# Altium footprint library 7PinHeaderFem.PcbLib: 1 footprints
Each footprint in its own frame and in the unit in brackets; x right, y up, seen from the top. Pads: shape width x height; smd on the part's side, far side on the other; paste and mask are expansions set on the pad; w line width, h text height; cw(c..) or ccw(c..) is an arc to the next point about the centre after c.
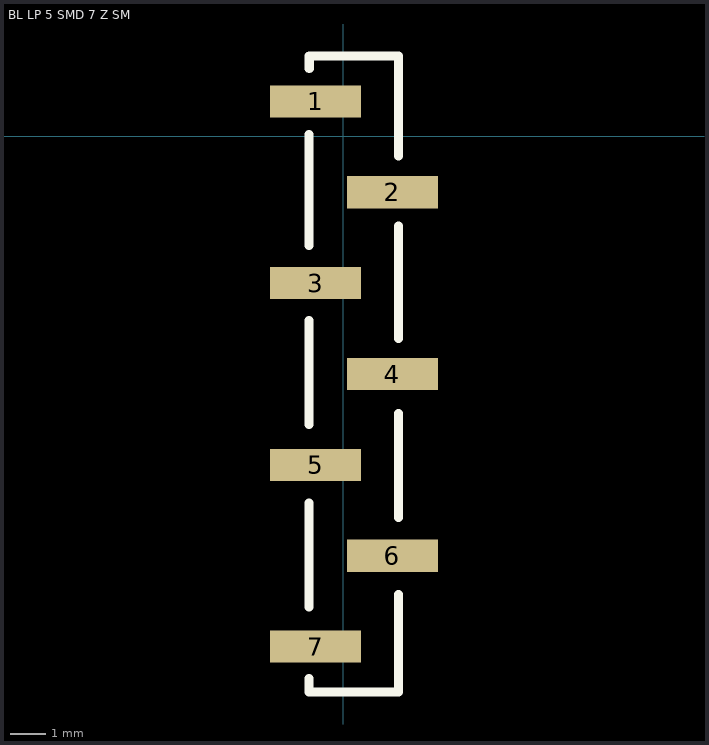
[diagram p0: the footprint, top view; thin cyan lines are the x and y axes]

## BL LP 5 SMD 7 Z SM [mm] "Fischer elektronik 7 pin female header. SMD."
height 0.4
pads (7):
  rect 2.55x0.9 smd: 1(-0.77,0.98) 2(1.38,-1.56) 3(-0.77,-4.1) 4(1.38,-6.64) 5(-0.77,-9.18) 6(1.38,-11.72) 7(-0.77,-14.26)
Top Overlay:
  lines w0.254: -0.95,-15.53 -0.95,-15.15 ; -0.95,-13.15 -0.95,-10.25 ; -0.95,-8.05 -0.95,-5.15 ; -0.95,-3.05 -0.95,0.05 ; -0.945,-15.53 1.55,-15.53 1.55,-12.8 ; -0.945,1.9 -0.945,2.25 1.55,2.25 1.55,-0.55 ; 1.55,-10.65 1.55,-7.75 ; 1.55,-5.65 1.55,-2.5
